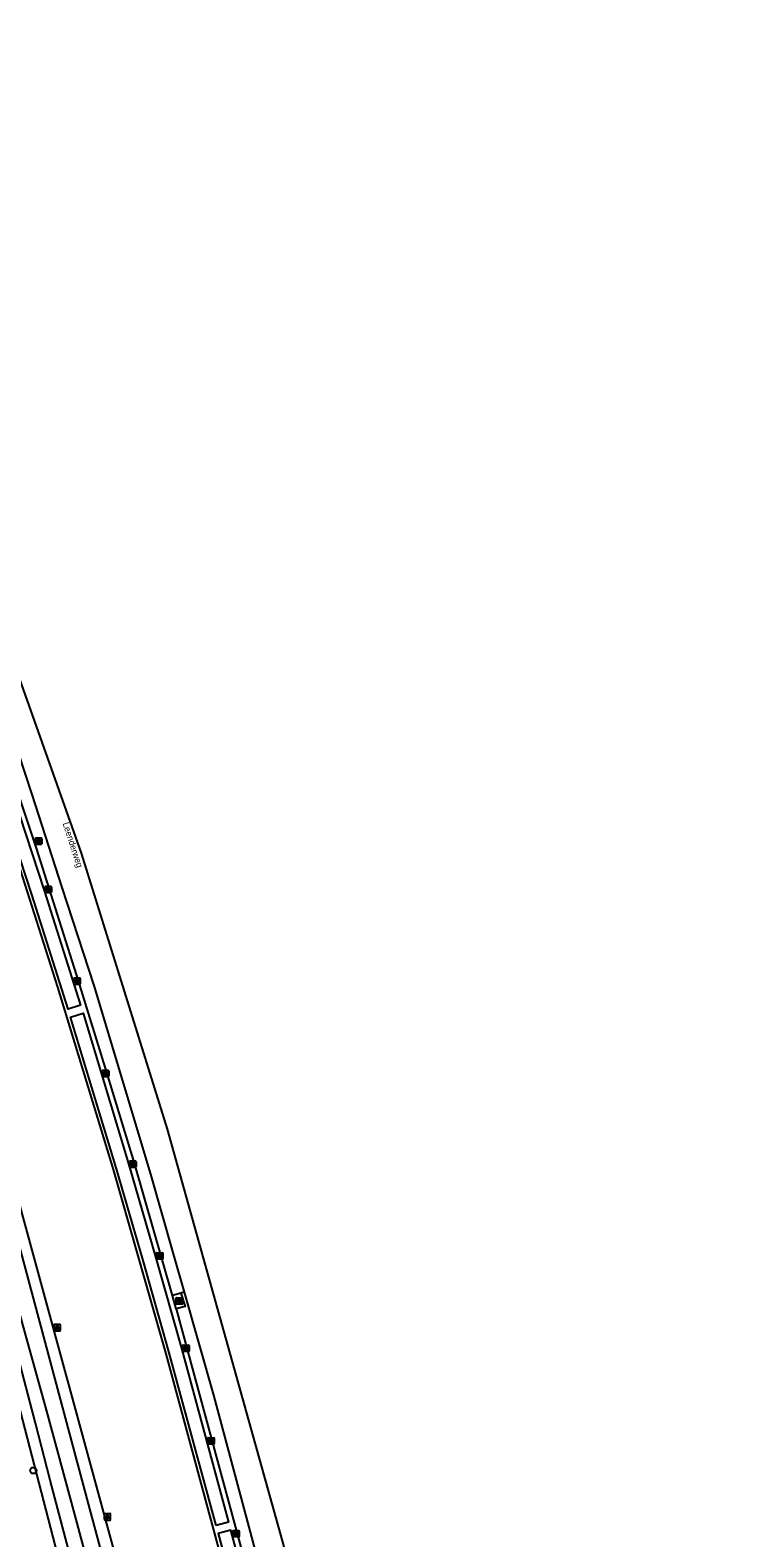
# Model space of a CAD drawing. Extents: x 162157 to 163165, y 378998 to 380775.
# Drawn here: x 162722.8 to 162833.2, y 380504.1 to 380739.7 of the extents above; entities that cross this region are included whole.
import ezdxf

# ---------------------------------------------------------------- set-up
doc = ezdxf.new("R2010")
doc.units = 0
for name, color, linetype in [('IMGEO_Berm_groen', 7, 'Continuous'), ('IMGEO_Boom', 7, 'Continuous'), ('IMGEO_Fietspad_gesloten', 7, 'Continuous'), ('IMGEO_Kolk', 7, 'Continuous'), ('IMGEO_Lichtpunt', 7, 'Continuous'), ('IMGEO_Muur', 7, 'Continuous'), ('IMGEO_Openbare_ruimte_label', 7, 'Continuous'), ('IMGEO_Rijbaan_lokaal_onverhard', 7, 'Continuous'), ('IMGEO_Rijbaan_regionaal_gesloten', 7, 'Continuous'), ('IMGEO_Rioolput', 7, 'Continuous'), ('IMGEO_Voetpad_open', 7, 'Continuous')]:
    doc.layers.add(name, color=color, linetype=linetype)

msp = doc.modelspace()

# ---------------------------------------------------------------- linework, layer by layer
at = {"layer": 'IMGEO_Berm_groen'}
for points in [[(162737.51, 380495.43), (162737.14, 380497.52), (162736.46, 380500), (162689.37, 380672.38)], [(162746.32, 380542.35), (162744.99, 380541.98)], [(162746.32, 380542.35), (162746.98, 380540.24), (162745.6, 380539.88)], [(162746.82, 380542.49), (162746.32, 380542.35)]]:
    msp.add_lwpolyline(points, dxfattribs=at)
at = {"layer": 'IMGEO_Boom'}
msp.add_circle((162723.27, 380514.63), 0.489, dxfattribs=at)
at = {"layer": 'IMGEO_Fietspad_gesloten'}
for points in [[(162731.28, 380485.43), (162727.48, 380500), (162708.82, 380571.72), (162678.5, 380685.89), (162676.54, 380692.53), (162675.8, 380694.61)], [(162731.75, 380491.01), (162729.37, 380500), (162728.76, 380502.29), (162725.91, 380513.1), (162723.6, 380522.01), (162720.62, 380533.4), (162716.62, 380548.72), (162712.25, 380565.21), (162708.35, 380579.63), (162704.9, 380592.93), (162701, 380607.61), (162698.81, 380616.11), (162696.09, 380626.22), (162693.68, 380635.21), (162691.57, 380643.43), (162689.22, 380652.34), (162686.64, 380662.34), (162683.66, 380673.38), (162680.65, 380684.7), (162678.31, 380693.64), (162678.1, 380694.35)]]:
    msp.add_lwpolyline(points, dxfattribs=at)
at = {"layer": 'IMGEO_Kolk'}
for p, q in [((162725.08, 380604.99), (162725.08, 380605.85)), ((162725.16, 380605.92), (162726.01, 380605.92)), ((162726.08, 380605.85), (162726.08, 380604.99)), ((162726.01, 380604.92), (162725.16, 380604.92)), ((162725.57, 380605.7), (162725.59, 380605.7)), ((162725.59, 380605.14), (162725.57, 380605.14)), ((162729.6, 380590.66), (162729.6, 380591.52)), ((162729.67, 380591.59), (162730.53, 380591.59)), ((162730.53, 380590.59), (162729.67, 380590.59)), ((162730.11, 380590.81), (162730.08, 380590.81)), ((162730.09, 380591.37), (162730.11, 380591.37)), ((162730.6, 380591.52), (162730.6, 380590.66)), ((162734.03, 380576.23), (162734.03, 380577.09)), ((162734.11, 380577.16), (162734.96, 380577.16)), ((162734.96, 380576.16), (162734.11, 380576.16)), ((162734.52, 380576.94), (162734.55, 380576.94)), ((162734.54, 380576.38), (162734.52, 380576.38)), ((162735.04, 380577.09), (162735.04, 380576.23)), ((162738.31, 380562.07), (162738.31, 380562.92)), ((162738.39, 380563), (162739.24, 380563)), ((162739.24, 380561.99), (162738.39, 380561.99)), ((162738.8, 380562.77), (162738.82, 380562.77)), ((162738.82, 380562.22), (162738.8, 380562.22)), ((162739.31, 380562.92), (162739.31, 380562.07)), ((162742.51, 380547.73), (162742.51, 380548.58)), ((162742.58, 380548.65), (162743.43, 380548.65)), ((162743.43, 380547.65), (162742.58, 380547.65)), ((162742.99, 380548.43), (162743.02, 380548.43)), ((162743.02, 380547.87), (162742.99, 380547.87)), ((162743.51, 380548.58), (162743.51, 380547.73)), ((162746.59, 380533.29), (162746.59, 380534.14)), ((162746.66, 380534.21), (162747.51, 380534.21)), ((162747.51, 380533.21), (162746.66, 380533.21)), ((162747.07, 380533.99), (162747.1, 380533.99)), ((162747.1, 380533.43), (162747.07, 380533.43)), ((162747.59, 380534.14), (162747.59, 380533.29)), ((162750.52, 380518.82), (162750.52, 380519.68)), ((162750.59, 380519.75), (162751.45, 380519.75)), ((162751.45, 380518.75), (162750.59, 380518.75)), ((162751.03, 380518.97), (162751, 380518.97)), ((162751.01, 380519.53), (162751.03, 380519.53)), ((162751.52, 380519.68), (162751.52, 380518.82)), ((162754.43, 380504.31), (162754.43, 380505.17)), ((162754.5, 380505.24), (162755.36, 380505.24)), ((162754.92, 380505.02), (162754.94, 380505.02)), ((162754.94, 380504.46), (162754.92, 380504.46)), ((162755.43, 380505.17), (162755.43, 380504.31)), ((162755.36, 380504.24), (162754.5, 380504.24))]:
    msp.add_line(p, q, dxfattribs=at)
for points in [[(162725.08, 380604.99), (162725.08, 380605.85)], [(162725.16, 380605.92), (162726.01, 380605.92)], [(162726.08, 380605.85), (162726.08, 380604.99)], [(162726.01, 380604.92), (162725.16, 380604.92)], [(162725.4, 380605.62), (162725.53, 380605.62), (162725.53, 380605.47), (162725.65, 380605.62), (162725.82, 380605.62), (162725.67, 380605.47), (162725.83, 380605.22), (162725.67, 380605.22), (162725.59, 380605.39), (162725.53, 380605.32), (162725.53, 380605.22), (162725.4, 380605.22), (162725.4, 380605.62)], [(162729.6, 380590.66), (162729.6, 380591.52)], [(162729.67, 380591.59), (162730.53, 380591.59)], [(162730.53, 380590.59), (162729.67, 380590.59)], [(162729.92, 380591.29), (162730.04, 380591.29), (162730.04, 380591.14), (162730.17, 380591.29), (162730.34, 380591.29), (162730.19, 380591.14), (162730.34, 380590.89), (162730.19, 380590.89), (162730.11, 380591.05), (162730.04, 380590.99), (162730.04, 380590.89), (162729.92, 380590.89), (162729.92, 380591.29)], [(162730.6, 380591.52), (162730.6, 380590.66)], [(162734.03, 380576.23), (162734.03, 380577.09)], [(162734.11, 380577.16), (162734.96, 380577.16)], [(162734.96, 380576.16), (162734.11, 380576.16)], [(162734.35, 380576.86), (162734.48, 380576.86), (162734.48, 380576.71), (162734.61, 380576.86), (162734.77, 380576.86), (162734.63, 380576.71), (162734.78, 380576.46), (162734.63, 380576.46), (162734.54, 380576.63), (162734.48, 380576.56), (162734.48, 380576.46), (162734.35, 380576.46), (162734.35, 380576.86)], [(162735.04, 380577.09), (162735.04, 380576.23)], [(162738.31, 380562.07), (162738.31, 380562.92)], [(162738.39, 380563), (162739.24, 380563)], [(162739.24, 380561.99), (162738.39, 380561.99)], [(162738.63, 380562.69), (162738.76, 380562.69), (162738.76, 380562.54), (162738.88, 380562.69), (162739.05, 380562.69), (162738.9, 380562.54), (162739.06, 380562.29), (162738.9, 380562.29), (162738.82, 380562.46), (162738.76, 380562.39), (162738.76, 380562.29), (162738.63, 380562.29), (162738.63, 380562.69)], [(162739.31, 380562.92), (162739.31, 380562.07)], [(162742.51, 380547.73), (162742.51, 380548.58)], [(162742.58, 380548.65), (162743.43, 380548.65)], [(162743.43, 380547.65), (162742.58, 380547.65)], [(162742.83, 380548.35), (162742.95, 380548.35), (162742.95, 380548.2), (162743.08, 380548.35), (162743.24, 380548.35), (162743.1, 380548.2), (162743.25, 380547.95), (162743.1, 380547.95), (162743.01, 380548.12), (162742.95, 380548.05), (162742.95, 380547.95), (162742.83, 380547.95), (162742.83, 380548.35)], [(162743.51, 380548.58), (162743.51, 380547.73)], [(162746.59, 380533.29), (162746.59, 380534.14)], [(162746.66, 380534.21), (162747.51, 380534.21)], [(162747.51, 380533.21), (162746.66, 380533.21)], [(162746.91, 380533.91), (162747.03, 380533.91), (162747.03, 380533.76), (162747.16, 380533.91), (162747.32, 380533.91), (162747.18, 380533.76), (162747.33, 380533.51), (162747.18, 380533.51), (162747.09, 380533.68), (162747.03, 380533.61), (162747.03, 380533.51), (162746.91, 380533.51), (162746.91, 380533.91)], [(162747.59, 380534.14), (162747.59, 380533.29)], [(162750.52, 380518.82), (162750.52, 380519.68)], [(162750.59, 380519.75), (162751.45, 380519.75)], [(162751.45, 380518.75), (162750.59, 380518.75)], [(162750.84, 380519.45), (162750.96, 380519.45), (162750.96, 380519.3), (162751.09, 380519.45), (162751.26, 380519.45), (162751.11, 380519.3), (162751.26, 380519.05), (162751.11, 380519.05), (162751.03, 380519.21), (162750.96, 380519.15), (162750.96, 380519.05), (162750.84, 380519.05), (162750.84, 380519.45)], [(162751.52, 380519.68), (162751.52, 380518.82)], [(162754.43, 380504.31), (162754.43, 380505.17)], [(162754.5, 380505.24), (162755.36, 380505.24)], [(162754.75, 380504.94), (162754.87, 380504.94), (162754.87, 380504.79), (162755, 380504.94), (162755.17, 380504.94), (162755.02, 380504.79), (162755.17, 380504.54), (162755.02, 380504.54), (162754.94, 380504.71), (162754.87, 380504.64), (162754.87, 380504.54), (162754.75, 380504.54), (162754.75, 380504.94)], [(162755.43, 380505.17), (162755.43, 380504.31)], [(162755.36, 380504.24), (162754.5, 380504.24)]]:
    msp.add_lwpolyline(points, dxfattribs=at)
for centre, start, end in [((162725.16, 380605.85), 91.552, 178.448), ((162725.16, 380605.85), 91.552, 178.448), ((162726.01, 380605.85), 1.552, 88.448), ((162726.01, 380605.85), 1.552, 88.448), ((162725.16, 380605), 181.552, 268.448), ((162725.16, 380605), 181.552, 268.448), ((162726.01, 380605), 271.552, 358.448), ((162726.01, 380605), 271.552, 358.448), ((162729.68, 380591.51), 91.552, 178.448), ((162729.68, 380591.51), 91.552, 178.448), ((162729.68, 380590.67), 181.552, 268.448), ((162729.68, 380590.67), 181.552, 268.448), ((162730.52, 380591.51), 1.552, 88.448), ((162730.52, 380591.51), 1.552, 88.448), ((162730.52, 380590.67), 271.552, 358.448), ((162730.52, 380590.67), 271.552, 358.448), ((162734.11, 380577.09), 91.552, 178.448), ((162734.11, 380577.09), 91.552, 178.448), ((162734.11, 380576.24), 181.552, 268.448), ((162734.11, 380576.24), 181.552, 268.448), ((162734.96, 380577.09), 1.552, 88.448), ((162734.96, 380577.09), 1.552, 88.448), ((162734.96, 380576.24), 271.552, 358.448), ((162734.96, 380576.24), 271.552, 358.448), ((162738.39, 380562.92), 91.552, 178.448), ((162738.39, 380562.92), 91.552, 178.448), ((162738.39, 380562.07), 181.552, 268.448), ((162738.39, 380562.07), 181.552, 268.448), ((162739.24, 380562.92), 1.552, 88.448), ((162739.24, 380562.92), 1.552, 88.448), ((162739.24, 380562.07), 271.552, 358.448), ((162739.24, 380562.07), 271.552, 358.448), ((162742.58, 380548.58), 91.552, 178.448), ((162742.58, 380548.58), 91.552, 178.448), ((162742.58, 380547.73), 181.552, 268.448), ((162742.58, 380547.73), 181.552, 268.448), ((162743.43, 380548.58), 1.552, 88.448), ((162743.43, 380548.58), 1.552, 88.448), ((162743.43, 380547.73), 271.552, 358.448), ((162743.43, 380547.73), 271.552, 358.448), ((162746.66, 380534.14), 91.552, 178.448), ((162746.66, 380534.14), 91.552, 178.448), ((162746.66, 380533.29), 181.552, 268.448), ((162746.66, 380533.29), 181.552, 268.448), ((162747.51, 380534.14), 1.552, 88.448), ((162747.51, 380534.14), 1.552, 88.448), ((162747.51, 380533.29), 271.552, 358.448), ((162747.51, 380533.29), 271.552, 358.448), ((162750.6, 380519.67), 91.552, 178.448), ((162750.6, 380519.67), 91.552, 178.448), ((162750.6, 380518.83), 181.552, 268.448), ((162750.6, 380518.83), 181.552, 268.448), ((162751.44, 380519.67), 1.552, 88.448), ((162751.44, 380519.67), 1.552, 88.448), ((162751.44, 380518.83), 271.552, 358.448), ((162751.44, 380518.83), 271.552, 358.448), ((162754.51, 380505.17), 91.552, 178.448), ((162754.51, 380505.17), 91.552, 178.448), ((162755.35, 380505.17), 1.552, 88.448), ((162755.35, 380505.17), 1.552, 88.448), ((162754.51, 380504.32), 181.552, 268.448), ((162754.51, 380504.32), 181.552, 268.448), ((162755.35, 380504.32), 271.552, 358.448), ((162755.35, 380504.32), 271.552, 358.448)]:
    msp.add_arc(centre, 0.0765, start, end, dxfattribs=at)
for centre, major_axis, ratio, start_param, end_param in [((162725.57, 380605.42), (-0.387, 0.002), 0.722429, 4.712389, 7.853982), ((162725.59, 380605.42), (-0.39, 0.002), 0.717154, 1.570796, 4.712389), ((162730.09, 380591.09), (-0.387, 0.002), 0.722429, 4.712389, 7.853982), ((162730.11, 380591.09), (-0.39, 0.002), 0.717154, 1.570796, 4.712389), ((162734.52, 380576.66), (-0.387, 0.002), 0.722429, 4.712389, 7.853982), ((162734.55, 380576.66), (-0.39, 0.002), 0.717154, 1.570796, 4.712389), ((162738.8, 380562.49), (-0.387, 0.002), 0.722429, 4.712389, 7.853982), ((162738.82, 380562.49), (-0.39, 0.002), 0.717154, 1.570796, 4.712389), ((162742.99, 380548.15), (-0.387, 0.002), 0.722429, 4.712389, 7.853982), ((162743.02, 380548.15), (-0.39, 0.002), 0.717154, 1.570796, 4.712389), ((162747.07, 380533.71), (-0.387, 0.002), 0.722429, 4.712389, 7.853982), ((162747.1, 380533.71), (-0.39, 0.002), 0.717154, 1.570796, 4.712389), ((162751.01, 380519.25), (-0.387, 0.002), 0.722429, 4.712389, 7.853982), ((162751.03, 380519.25), (-0.39, 0.002), 0.717154, 1.570796, 4.712389), ((162754.92, 380504.74), (-0.387, 0.002), 0.722429, 4.712389, 7.853982), ((162754.94, 380504.74), (-0.39, 0.002), 0.717154, 1.570796, 4.712389)]:
    msp.add_ellipse(centre, major_axis=major_axis, ratio=ratio, start_param=start_param, end_param=end_param, dxfattribs=at)
at = {"layer": 'IMGEO_Lichtpunt'}
for p, q in [((162727.4, 380537.44), (162726.59, 380537.44)), ((162727.4, 380537.44), (162726.59, 380537.44)), ((162726.5, 380537.35), (162726.5, 380536.54)), ((162726.5, 380537.35), (162726.5, 380536.54)), ((162726.59, 380536.44), (162727.4, 380536.44)), ((162726.59, 380536.44), (162727.4, 380536.44)), ((162727.49, 380536.54), (162727.49, 380537.35)), ((162727.49, 380536.54), (162727.49, 380537.35)), ((162734.34, 380507.79), (162734.34, 380506.98)), ((162734.34, 380507.79), (162734.34, 380506.98)), ((162735.24, 380507.88), (162734.43, 380507.88)), ((162735.24, 380507.88), (162734.43, 380507.88)), ((162734.43, 380506.88), (162735.24, 380506.88)), ((162734.43, 380506.88), (162735.24, 380506.88)), ((162735.33, 380506.98), (162735.33, 380507.79)), ((162735.33, 380506.98), (162735.33, 380507.79))]:
    msp.add_line(p, q, dxfattribs=at)
for points in [[(162726.87, 380537.01), (162726.91, 380536.98), (162726.72, 380536.72), (162726.68, 380536.75), (162726.87, 380537.01)], [(162726.97, 380536.96), (162727.02, 380536.96), (162727.02, 380536.64), (162726.97, 380536.64), (162726.97, 380536.96)], [(162727.08, 380536.98), (162727.12, 380537.01), (162727.31, 380536.75), (162727.27, 380536.72), (162727.08, 380536.98)], [(162734.71, 380507.45), (162734.75, 380507.42), (162734.56, 380507.16), (162734.52, 380507.19), (162734.71, 380507.45)], [(162734.81, 380507.4), (162734.86, 380507.4), (162734.86, 380507.08), (162734.81, 380507.08), (162734.81, 380507.4)], [(162734.92, 380507.42), (162734.96, 380507.45), (162735.15, 380507.19), (162735.11, 380507.16), (162734.92, 380507.42)]]:
    msp.add_lwpolyline(points, dxfattribs=at)
for centre in [(162727, 380537.14), (162734.84, 380507.58)]:
    msp.add_circle(centre, 0.0994, dxfattribs=at)
for centre, start, end in [((162726.59, 380537.35), 90, 180), ((162726.59, 380537.35), 90, 180), ((162727.4, 380537.35), 0, 90), ((162727.4, 380537.35), 0, 90), ((162726.59, 380536.54), 180, 270), ((162726.59, 380536.54), 180, 270), ((162727.4, 380536.54), 270, 0), ((162727.4, 380536.54), 270, 360), ((162734.43, 380507.79), 90, 180), ((162734.43, 380507.79), 90, 180), ((162734.43, 380506.98), 180, 270), ((162734.43, 380506.98), 180, 270), ((162735.24, 380507.79), 0, 90), ((162735.24, 380507.79), 0, 90), ((162735.24, 380506.98), 270, 0), ((162735.24, 380506.98), 270, 360)]:
    msp.add_arc(centre, 0.0946, start, end, dxfattribs=at)
at = {"layer": 'IMGEO_Muur'}
for points in [[(162703.46, 380661.41), (162698.74, 380674.06), (162688.87, 380676.77), (162689.45, 380678.73), (162700.27, 380675.73), (162705.36, 380662.11), (162710.64, 380647.43), (162715.45, 380633.76), (162720.23, 380619.73), (162724.97, 380605.24), (162730.64, 380587.33), (162728.7, 380586.72), (162723.05, 380604.63), (162718.31, 380619.09), (162713.54, 380633.1), (162706.35, 380653.38), (162703.46, 380661.41)], [(162751.82, 380506.01), (162744.5, 380532.99), (162740.43, 380547.44), (162736.24, 380561.79), (162729.09, 380585.48), (162731.03, 380586.07), (162738.18, 380562.37), (162742.37, 380548), (162746.45, 380533.53), (162753.77, 380506.54), (162751.82, 380506.01)], [(162778.95, 380394), (162782.38, 380400.32), (162763.72, 380469.64), (162754.13, 380505.29), (162752.17, 380504.76), (162761.77, 380469.11), (162780.22, 380400.58), (162777.21, 380394.95)]]:
    msp.add_lwpolyline(points, dxfattribs=at)
at = {"layer": 'IMGEO_Rijbaan_lokaal_onverhard'}
for points in [[(162731.86, 380500), (162731.54, 380501.15), (162730.12, 380506.4), (162727.86, 380514.69), (162725.37, 380523.9), (162721.95, 380536.28), (162719.71, 380544.43), (162717.7, 380551.87), (162715.8, 380559.17), (162709.63, 380583.26), (162699.68, 380620.37), (162691.68, 380650.23), (162687.5, 380663.09), (162687.02, 380664.95), (162684.5, 380674), (162682.06, 380682.8), (162679.01, 380694.22), (162678.36, 380695.48)], [(162689.37, 380672.38), (162689.07, 380670.45), (162699.19, 380631.13), (162717.6, 380562.41), (162731.81, 380509.4), (162737.13, 380489.66)]]:
    msp.add_lwpolyline(points, dxfattribs=at)
at = {"layer": 'IMGEO_Rijbaan_regionaal_gesloten'}
for points in [[(162683.4, 380739.7), (162691.09, 380720.33), (162695.16, 380708.96), (162706.16, 380680.31), (162730.73, 380611.09), (162744.15, 380567.96), (162763.14, 380500.1), (162770.9, 380471.58), (162776.29, 380450.02), (162815.72, 380304.13), (162827.68, 380257.65), (162833.19, 380237.78)], [(162703.79, 380674.62), (162706.76, 380666.41), (162715.8, 380641.76), (162717.45, 380636.6), (162720.83, 380626.94), (162723.01, 380620.24), (162727.72, 380605.72), (162732.7, 380590.39), (162741.57, 380560.91), (162745.12, 380548.47), (162746.82, 380542.49)], [(162746.82, 380542.49), (162751.4, 380526.42), (162757.93, 380502.08), (162763.52, 380481.21), (162769.54, 380458.74), (162777.14, 380430.38), (162785.23, 380400.19), (162788.69, 380387.26), (162795.79, 380360.77), (162800.79, 380342.1), (162806.62, 380320.37), (162813.55, 380294.48), (162819.58, 380271.99), (162825.25, 380250.82), (162829.03, 380236.7)]]:
    msp.add_lwpolyline(points, dxfattribs=at)
at = {"layer": 'IMGEO_Rioolput'}
for p, q in [((162723.56, 380612.55), (162723.56, 380613.4)), ((162723.64, 380613.48), (162724.49, 380613.48)), ((162724.05, 380613.25), (162724.08, 380613.25)), ((162724.57, 380613.4), (162724.57, 380612.55)), ((162724.49, 380612.47), (162723.64, 380612.47)), ((162724.07, 380612.7), (162724.05, 380612.7)), ((162745.59, 380540.69), (162745.59, 380541.55)), ((162745.66, 380541.62), (162746.51, 380541.62)), ((162746.51, 380540.62), (162745.66, 380540.62)), ((162746.1, 380540.84), (162746.07, 380540.84)), ((162746.08, 380541.4), (162746.1, 380541.4)), ((162746.59, 380541.55), (162746.59, 380540.69))]:
    msp.add_line(p, q, dxfattribs=at)
for points in [[(162723.56, 380612.55), (162723.56, 380613.4)], [(162723.64, 380613.48), (162724.49, 380613.48)], [(162724.15, 380613.17), (162723.9, 380613.17), (162723.9, 380612.77)], [(162723.9, 380612.77), (162724.03, 380612.77), (162724.03, 380612.94), (162724.04, 380612.94)], [(162724.08, 380613.09), (162724.03, 380613.09), (162724.03, 380613.01)], [(162724.03, 380613.01), (162724.08, 380613.01)], [(162724.08, 380612.91), (162724.15, 380612.77), (162724.29, 380612.77), (162724.23, 380612.9)], [(162724.57, 380613.4), (162724.57, 380612.55)], [(162724.49, 380612.47), (162723.64, 380612.47)], [(162745.59, 380540.69), (162745.59, 380541.55)], [(162745.66, 380541.62), (162746.51, 380541.62)], [(162746.51, 380540.62), (162745.66, 380540.62)], [(162746.18, 380541.32), (162745.92, 380541.32), (162745.92, 380540.92)], [(162745.92, 380540.92), (162746.05, 380540.92), (162746.05, 380541.08), (162746.06, 380541.08)], [(162746.1, 380541.24), (162746.05, 380541.24), (162746.05, 380541.16)], [(162746.05, 380541.16), (162746.1, 380541.16)], [(162746.11, 380541.05), (162746.18, 380540.92), (162746.32, 380540.92), (162746.25, 380541.05)], [(162746.59, 380541.55), (162746.59, 380540.69)]]:
    msp.add_lwpolyline(points, dxfattribs=at)
for centre, radius, start, end in [((162723.64, 380613.4), 0.0765, 91.552, 178.448), ((162723.64, 380613.4), 0.0765, 91.552, 178.448), ((162724.03, 380612.88), 0.0533, 26.0293, 88.6989), ((162724.08, 380613), 0.0964, 77.0061, 93.1865), ((162724.06, 380613.2), 0.19, 274.7715, 282.9687), ((162724.1, 380613.05), 0.0378, 276.6634, 79.6772), ((162724.15, 380613.06), 0.109, 350.3612, 89.416), ((162724.15, 380613.06), 0.112, 277.5842, 350.9817), ((162724.13, 380612.85), 0.108, 29.5134, 73.7905), ((162724.49, 380613.4), 0.0765, 1.552, 88.448), ((162724.49, 380613.4), 0.0765, 1.552, 88.448), ((162723.64, 380612.55), 0.0765, 181.552, 268.448), ((162723.64, 380612.55), 0.0765, 181.552, 268.448), ((162724.49, 380612.55), 0.0765, 271.552, 358.448), ((162724.49, 380612.55), 0.0765, 271.552, 358.448), ((162745.66, 380541.54), 0.0765, 91.552, 178.448), ((162745.66, 380541.54), 0.0765, 91.552, 178.448), ((162745.66, 380540.7), 0.0765, 181.552, 268.448), ((162745.66, 380540.7), 0.0765, 181.552, 268.448), ((162746.06, 380541.03), 0.0533, 26.0293, 88.6989), ((162746.11, 380541.14), 0.0964, 77.0061, 93.1865), ((162746.08, 380541.35), 0.19, 274.7715, 282.9687), ((162746.12, 380541.2), 0.0378, 276.6634, 79.6772), ((162746.18, 380541.21), 0.109, 350.3612, 89.416), ((162746.17, 380541.21), 0.112, 277.5842, 350.9817), ((162746.16, 380540.99), 0.108, 29.5134, 73.7905), ((162746.51, 380541.54), 0.0765, 1.552, 88.448), ((162746.51, 380541.54), 0.0765, 1.552, 88.448), ((162746.51, 380540.7), 0.0765, 271.552, 358.448), ((162746.51, 380540.7), 0.0765, 271.552, 358.448)]:
    msp.add_arc(centre, radius, start, end, dxfattribs=at)
for centre, major_axis, ratio, start_param, end_param in [((162724.05, 380612.97), (-0.387, 0.002), 0.722429, 4.712389, 7.853982), ((162724.08, 380612.97), (-0.39, 0.002), 0.717154, 1.570796, 4.712389), ((162746.07, 380541.12), (-0.387, 0.002), 0.722429, 4.712389, 7.853982), ((162746.1, 380541.12), (-0.39, 0.002), 0.717154, 1.570796, 4.712389)]:
    msp.add_ellipse(centre, major_axis=major_axis, ratio=ratio, start_param=start_param, end_param=end_param, dxfattribs=at)
at = {"layer": 'IMGEO_Voetpad_open'}
for points in [[(162776.75, 380395.21), (162779.69, 380400.57), (162761.38, 380468.72), (162744.03, 380532.86), (162735.8, 380561.65), (162727.08, 380590.13), (162720.55, 380610.78), (162713.1, 380632.9), (162708.25, 380646.67), (162703, 380661.28), (162698.33, 380673.69), (162688.26, 380676.43)], [(162744.99, 380541.98), (162739.05, 380562.64), (162734.75, 380576.81), (162730.32, 380591.15), (162723.76, 380611.86), (162716.3, 380634.02), (162711.44, 380647.82), (162706.17, 380662.47), (162701.17, 380675.78)], [(162745.6, 380539.88), (162744.99, 380541.98)], [(162745.6, 380539.88), (162764.65, 380469.6), (162783.31, 380400.13), (162779.72, 380393.58)]]:
    msp.add_lwpolyline(points, dxfattribs=at)

# ---------------------------------------------------------------- texts
at = {"layer": 'IMGEO_Openbare_ruimte_label'}
msp.add_text('Leenderweg', height=1, rotation=288.0001, dxfattribs=at).set_placement((162727.83, 380615.74))

doc.saveas('drawing.dxf')
